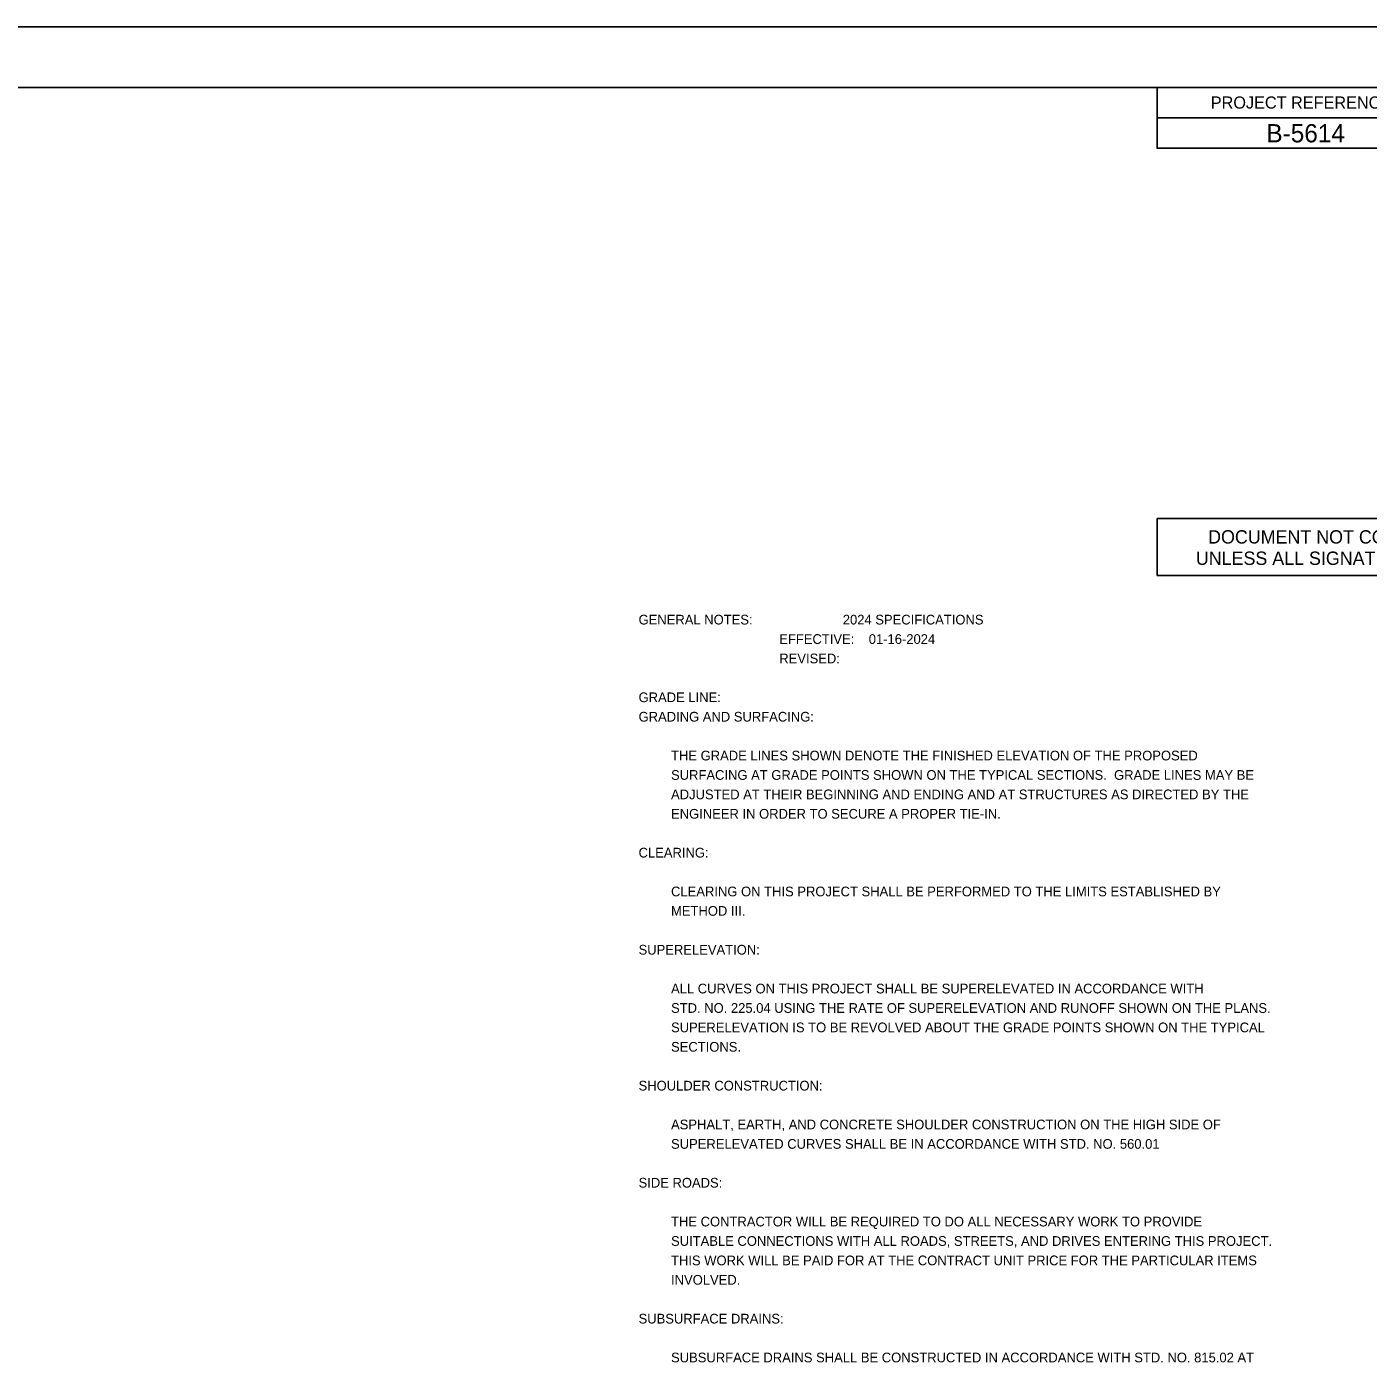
# Model space of a CAD drawing. Extents: x 885343.6 to 885383.5, y 651350.8 to 651372.8.
# Drawn here: x 885363.79 to 885374.84, y 651361.72 to 651372.76 of the extents above; entities that cross this region are included whole.
import ezdxf

# ---------------------------------------------------------------- set-up
doc = ezdxf.new("R2010")
doc.units = 0
for name, color, linetype in [('Scratch_Level_4', 7, 'Continuous'), ('Sheet Data Field CELL', 7, 'Continuous'), ('Sheet Data Text CELL', 7, 'Continuous'), ('Sheet Plan And Profile CELL', 7, 'Continuous'), ('Sheet Plan CELL', 7, 'Continuous'), ('Sheet Sticker Exception Certification CELL', 7, 'Continuous'), ('Stewart Plot Border Xerox6279 and LJ5000', 7, 'Continuous')]:
    doc.layers.add(name, color=color, linetype=linetype)

msp = doc.modelspace()

# ---------------------------------------------------------------- linework, layer by layer
at = {"layer": 'Scratch_Level_4'}
msp.add_line((885373.695, 651368.241), (885374.316, 651368.241), dxfattribs=at)
at = {"layer": 'Sheet Plan And Profile CELL'}
msp.add_line((885373.098, 651372.011), (885377.098, 651372.011), dxfattribs=at)
msp.add_lwpolyline([(885373.098, 651372.262), (885377.098, 651372.262), (885377.098, 651371.761), (885373.098, 651371.761)], close=True, dxfattribs=at)
at = {"layer": 'Sheet Plan CELL'}
msp.add_lwpolyline([(885377.098, 651372.262), (885347.098, 651372.262), (885347.098, 651351.262), (885377.098, 651351.262)], close=True, dxfattribs=at)
at = {"layer": 'Sheet Sticker Exception Certification CELL'}
for p, q in [((885373.098, 651368.241), (885373.098, 651368.711)), ((885373.098, 651368.711), (885377.098, 651368.711)), ((885377.098, 651368.241), (885373.098, 651368.241))]:
    msp.add_line(p, q, dxfattribs=at)
at = {"layer": 'Stewart Plot Border Xerox6279 and LJ5000'}
msp.add_lwpolyline([(885343.598, 651372.762), (885377.598, 651372.762), (885377.598, 651350.762), (885343.598, 651350.762)], close=True, dxfattribs=at)

# ---------------------------------------------------------------- texts
at = {"layer": 'Sheet Data Field CELL'}
msp.add_text('B-5614', height=0.15, rotation=0, dxfattribs=at).set_placement((885373.999, 651371.81))
at = {"layer": 'Sheet Data Text CELL'}
for s, p in [('GENERAL NOTES:                         2024 SPECIFICATIONS', (885368.827, 651367.837)), ('                                       EFFECTIVE:    01-16-2024', (885368.827, 651367.677)), ('                                       REVISED:      ', (885368.827, 651367.517)), ('GRADE LINE:  ', (885368.827, 651367.197)), ('GRADING AND SURFACING:  ', (885368.827, 651367.037)), ('         THE GRADE LINES SHOWN DENOTE THE FINISHED ELEVATION OF THE PROPOSED ', (885368.827, 651366.717)), ('         SURFACING AT GRADE POINTS SHOWN ON THE TYPICAL SECTIONS.  GRADE LINES MAY BE ', (885368.827, 651366.557)), ('         ADJUSTED AT THEIR BEGINNING AND ENDING AND AT STRUCTURES AS DIRECTED BY THE ', (885368.827, 651366.397)), ('         ENGINEER IN ORDER TO SECURE A PROPER TIE-IN.  ', (885368.827, 651366.237)), ('CLEARING:  ', (885368.827, 651365.917)), ('         CLEARING ON THIS PROJECT SHALL BE PERFORMED TO THE LIMITS ESTABLISHED BY ', (885368.827, 651365.597)), ('         METHOD III.', (885368.827, 651365.437)), ('SUPERELEVATION:  ', (885368.827, 651365.117)), ('         ALL CURVES ON THIS PROJECT SHALL BE SUPERELEVATED IN ACCORDANCE WITH', (885368.827, 651364.797)), ('         STD. NO. 225.04 USING THE RATE OF SUPERELEVATION AND RUNOFF SHOWN ON THE PLANS.', (885368.827, 651364.637)), ('         SUPERELEVATION IS TO BE REVOLVED ABOUT THE GRADE POINTS SHOWN ON THE TYPICAL ', (885368.827, 651364.477)), ('         SECTIONS.  ', (885368.827, 651364.317)), ('SHOULDER CONSTRUCTION:  ', (885368.827, 651363.997)), ('         ASPHALT, EARTH, AND CONCRETE SHOULDER CONSTRUCTION ON THE HIGH SIDE OF', (885368.827, 651363.677)), ('         SUPERELEVATED CURVES SHALL BE IN ACCORDANCE WITH STD. NO. 560.01', (885368.827, 651363.517)), ('SIDE ROADS:  ', (885368.827, 651363.197)), ('         THE CONTRACTOR WILL BE REQUIRED TO DO ALL NECESSARY WORK TO PROVIDE ', (885368.827, 651362.877)), ('         SUITABLE CONNECTIONS WITH ALL ROADS, STREETS, AND DRIVES ENTERING THIS PROJECT.  ', (885368.827, 651362.717)), ('         THIS WORK WILL BE PAID FOR AT THE CONTRACT UNIT PRICE FOR THE PARTICULAR ITEMS ', (885368.827, 651362.557)), ('         INVOLVED.  ', (885368.827, 651362.397)), ('SUBSURFACE DRAINS:', (885368.827, 651362.077)), ('         SUBSURFACE DRAINS SHALL BE CONSTRUCTED IN ACCORDANCE WITH STD. NO. 815.02 AT ', (885368.827, 651361.757))]:
    msp.add_text(s, height=0.08, dxfattribs=at).set_placement(p)
at = {"layer": 'Sheet Plan And Profile CELL'}
msp.add_text('PROJECT REFERENCE NO.', height=0.1, rotation=0, dxfattribs=at).set_placement((885373.541, 651372.088))
at = {"layer": 'Sheet Sticker Exception Certification CELL'}
for s, p in [('DOCUMENT NOT CONSIDERED FINAL', (885373.519, 651368.504)), ('UNLESS ALL SIGNATURES COMPLETED', (885373.418, 651368.328))]:
    msp.add_text(s, height=0.11, rotation=0, dxfattribs=at).set_placement(p)

doc.saveas('drawing.dxf')
